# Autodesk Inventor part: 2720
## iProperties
Author: Administrator
Shininess: 64.0
Angle Display Precision: 2
Document Length Units: 11272
Document Angle Units: 11286
Document Time Units: 11279
Document Mass Units: 11290
Document Length Units Precision: 3
Document Angle Units Precision: 2
Compacted: True
PropertySet Name: _Private Model Information
Created: 2002-03
Part Number: 2720
Material: Stainless Steel, 440C
Document SubType Name: Modeling
Designer: Administrator
Control State: 0
Master: False
Checked Out: False
PropertySet Name: Design Tracking Control
Density: 0.0
Volumn: 0.0
Area: 0.0
PropertySet Name: Model Information
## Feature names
1. Revolution1
